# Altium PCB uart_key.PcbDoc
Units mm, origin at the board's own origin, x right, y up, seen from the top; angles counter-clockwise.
Board outline 80.99 x 54 mm, 2 copper layers (Top Layer, Bottom Layer); 61 components, 43 nets, 209 pads, 89 vias.
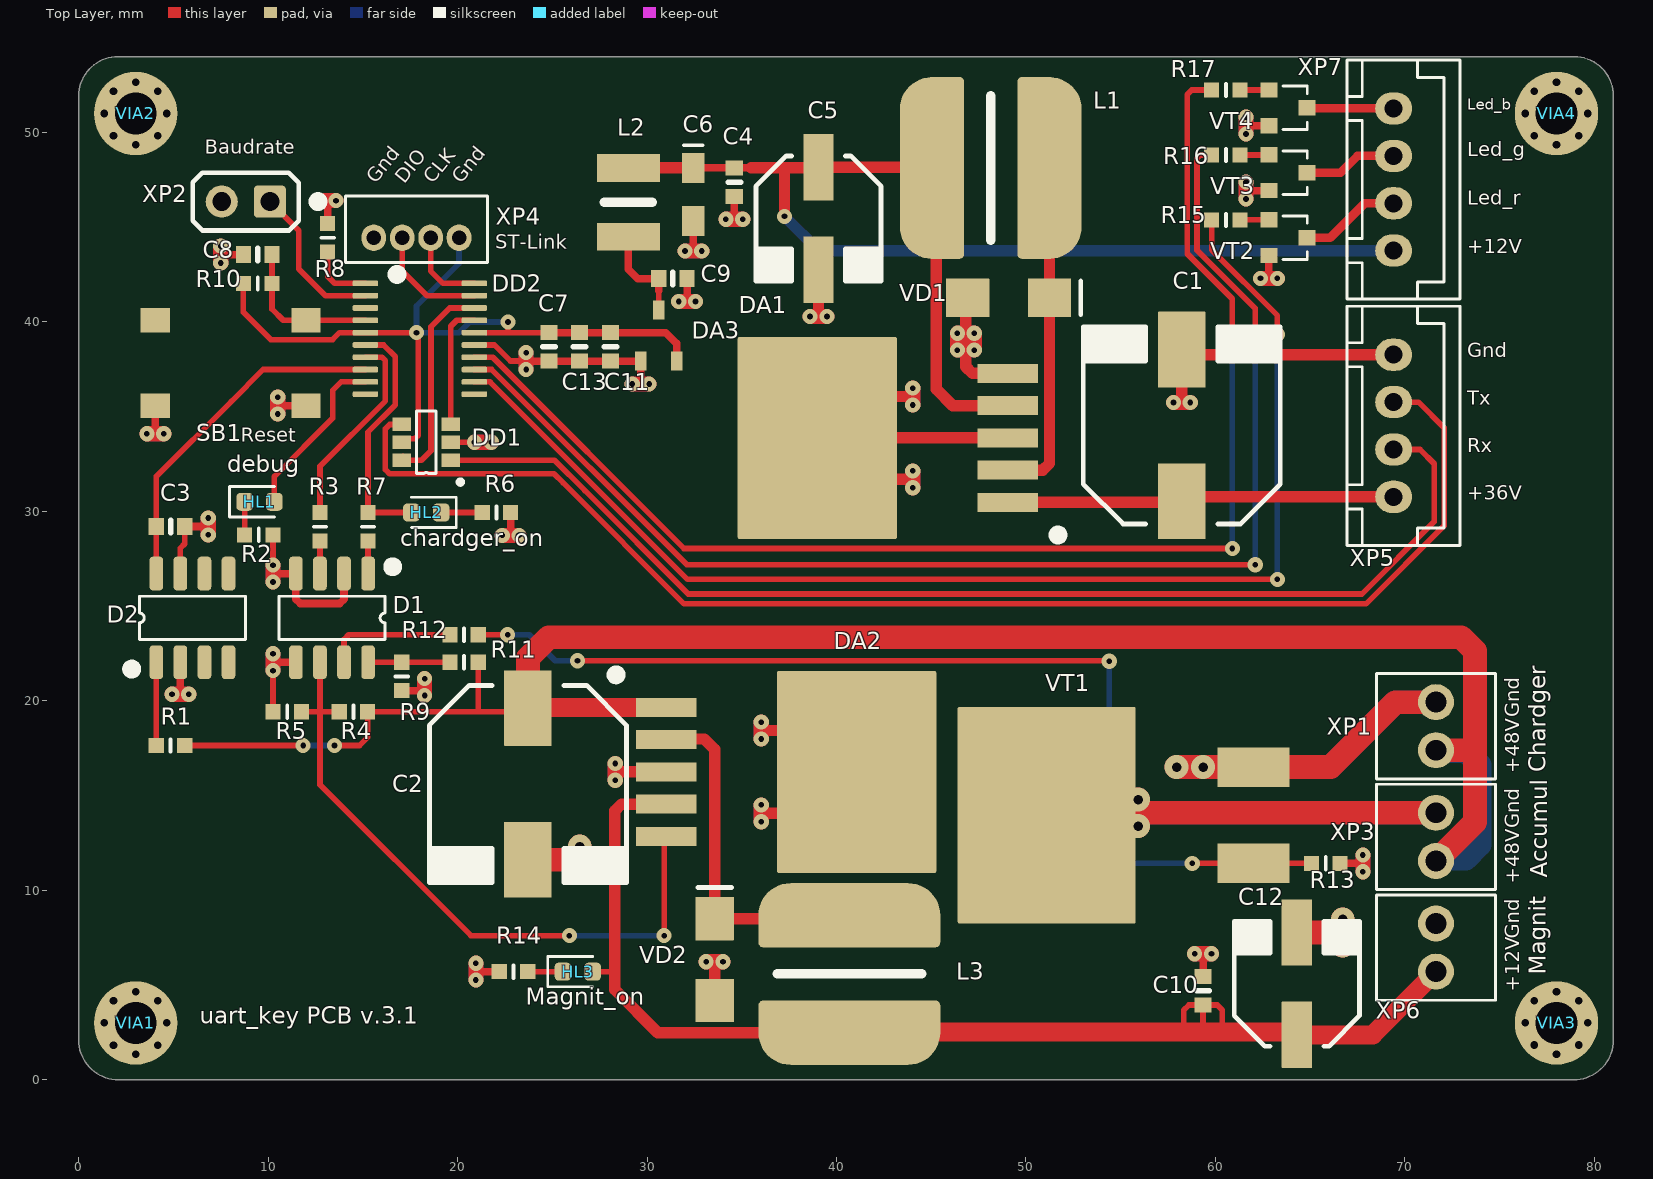
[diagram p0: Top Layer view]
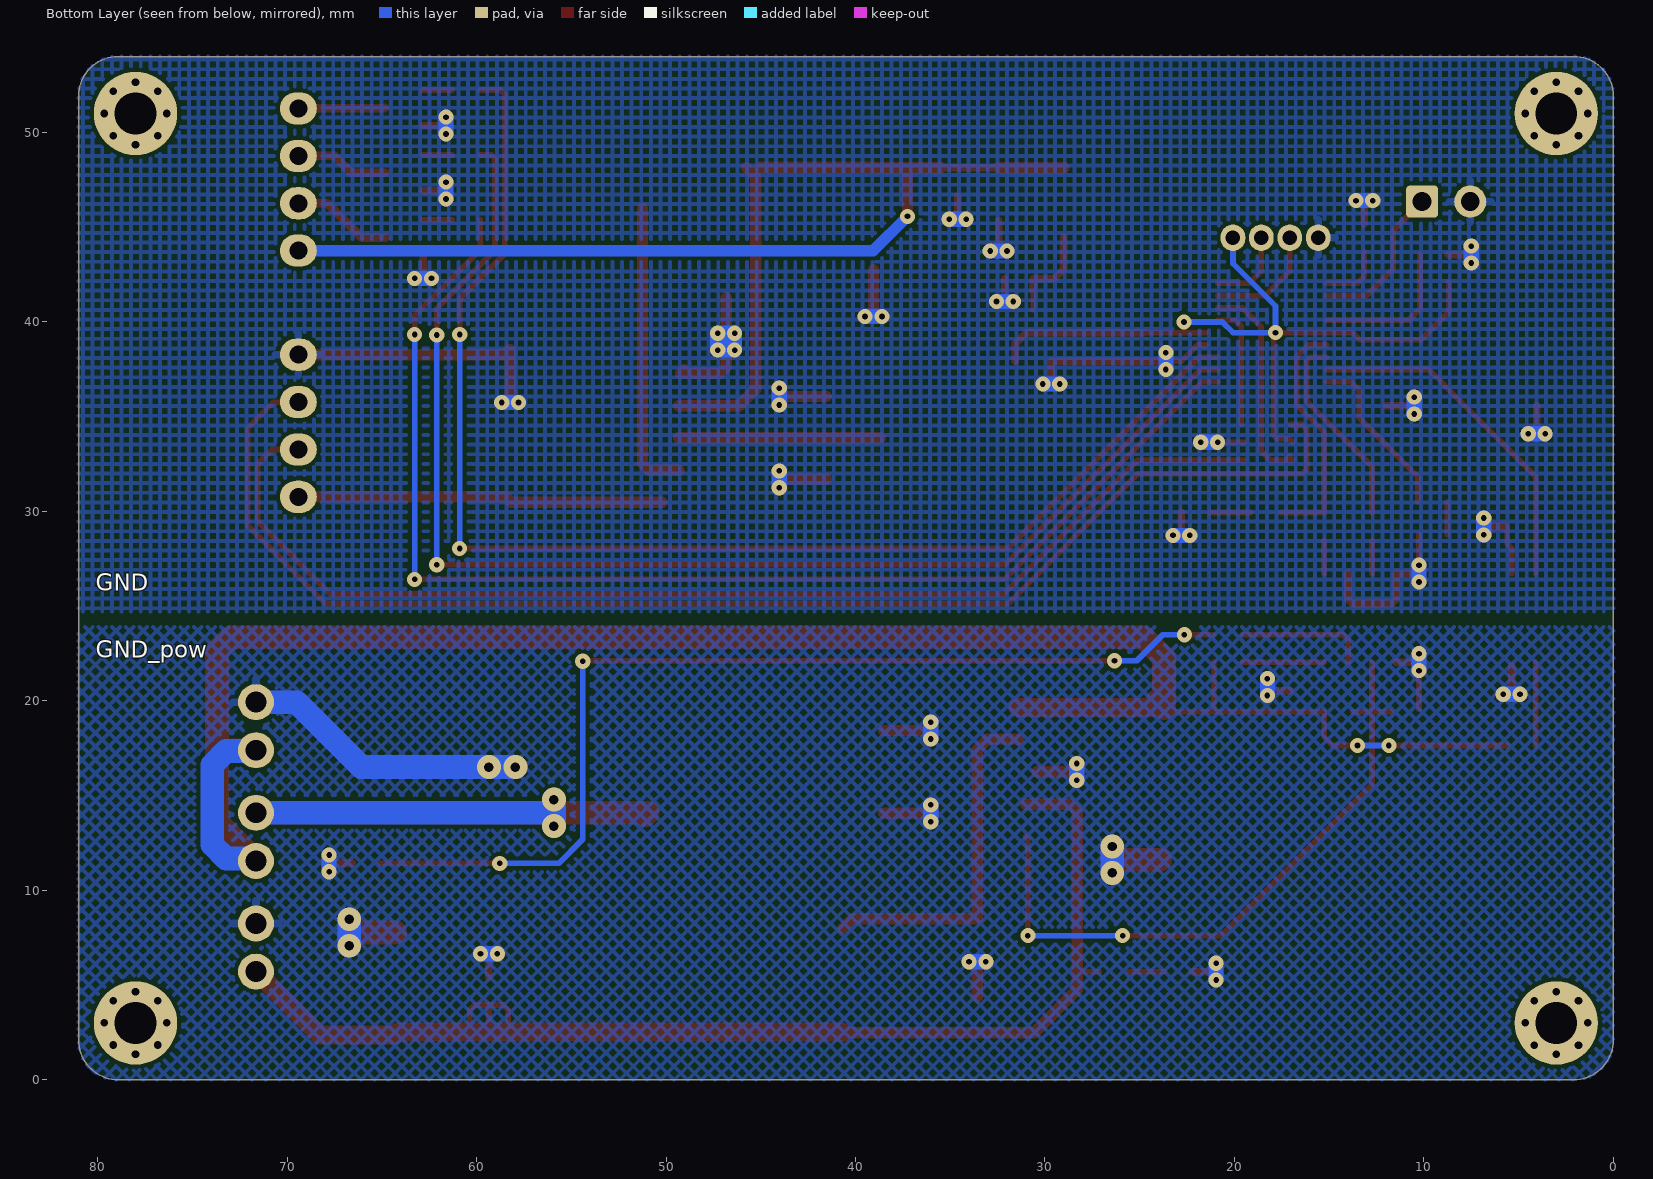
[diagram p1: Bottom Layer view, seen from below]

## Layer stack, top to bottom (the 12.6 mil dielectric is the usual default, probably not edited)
Top Solder: solder mask 0.0102, Solder Resist, Dk 3.5
Top Layer: signal copper 0.0356
Dielectric 1: dielectric 0.32, FR-4, Dk 4.8
Bottom Layer: signal copper 0.0356
Bottom Solder: solder mask 0.0102, Solder Resist, Dk 3.5

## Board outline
0.006,2.084 0.006,51.924 cw(c2.076,51.924) 2.076,53.994 78.931,53.994 cw(c78.93,51.924) 81,51.924 81,2.084 cw(c78.909,2.084) 78.909,-0.007 2.097,-0.006 cw(c2.097,2.084)

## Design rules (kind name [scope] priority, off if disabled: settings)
Clearance TestPointToPad [HasFootprint('TP_36_PAD') or HasFootprint('TP_38_PAD') or HasFootprint('TP_47_PAD') or HasFootprint('TP_50_PAD') or HasFootprint('TP_60_PAD') or HasFootprint('TP_80_PAD') or HasFootprint('TP_100_PAD') vs IsPad] p1: gap=0.22 ignorepadtopadclearanceinfootprint=FALSE except(0: Arc-Hole Track-Hole SMDPad-Hole THPad-Hole Via-Hole Fill-Hole Poly-Hole Region-Hole Text-Hole; 2: Arc-THPad Track-THPad SMDPad-THPad THPad-THPad)
Clearance [All] p2: gap=0.2 ignorepadtopadclearanceinfootprint=FALSE
ComponentClearance TestpointClearance [Footprint Like 'TP_36_PAD' or Footprint Like 'TP_38_PAD' or Footprint Like 'TP_47_PAD' or Footprint Like 'TP_50_PAD' or Footprint Like 'TP_60_PAD' or Footprint Like 'TP_80_PAD' or Footprint Like 'TP_100_PAD' vs Footprint Like 'TP_36_PAD' or Footprint Like 'TP_38_PAD' or Footprint Like 'TP_47_PAD' or Footprint Like 'TP_50_PAD' or Footprint Like 'TP_60_PAD' or Footprint Like 'TP_80_PAD' or Footprint Like 'TP_100_PAD'] p1: gap=0 collisioncheckmode=3 verticalgap=0.254 showdistances=FALSE
ComponentClearance [All] p2: gap=0.254 collisioncheckmode=3 verticalgap=0.254 showdistances=FALSE
DiffPairsRouting [All] p1: maxlimit=0.25 minlimit=0.2 mostfreqgap=0.22 toplayer_minwidth=0.2 toplayer_maxwidth=0.25 toplayer_prefwidth=0.22 bottomlayer_minwidth=0.2 bottomlayer_maxwidth=0.25 bottomlayer_prefwidth=0.22 maxuncoupledlength=12.7
HoleSize [All] p1: absolutevalues=TRUE maxlimit=4 minlimit=0.3 maxpercent=80.000 minpercent=20.000
MinimumSolderMaskSliver [All] p1: minsoldermaskwidth=0.1
PasteMaskExpansion [All] p1: expansion=-0.05
PlaneConnect [All] p1: planeconnectstyle=Relief reliefexpansion=0.508 reliefentries=4 reliefconductorwidth=0.4 reliefairgap=0.25
PolygonConnect PolygonConnect_1 [IsVia or InPadClass('Direct')] p1: connectstyle=Direct reliefconductorwidth=0.254 reliefentries=4 polygonreliefangle="90 Angle" airgapwidth=0.254
PolygonConnect [All] p2: connectstyle=Relief reliefconductorwidth=0.4 reliefentries=4 polygonreliefangle="90 Angle" airgapwidth=0.25
RoutingVias [All] p1: holewidth=0.3 width=1 viastyle="Through Hole" minholewidth=0.3 minwidth=0.7 maxholewidth=0.4 maxwidth=2.8
SilkToSilkClearance [All] p1: silktosilkclearance=0.2
SilkToSolderMaskClearance [IsPad] p1: minsilkscreentomaskgap=0.2 clearancetoexposedcopper=TRUE
SolderMaskExpansion [All] p1: expansion=0.1 istentingtop=FALSE
Width [All] p1: maxlimit=4 minlimit=0.22 preferedwidth=0.4
22 further rules are at their usual default settings.

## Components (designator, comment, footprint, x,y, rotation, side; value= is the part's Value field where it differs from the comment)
C1 "220uF 50V" CAPAE_SMD_1010 58.225,34.531 r270 top value=220uF
C2 "220uF 50V" CAPAE_SMD_1010 23.712,15.608 r90 top value=220uF
C3 "1uF 25V" CC0603_0.8mm 4.85,29.197 r0 top value=1uF
C4 "1uF 25V" CC0603_0.8mm 34.603,47.37 r270 top value=1uF
C5 "220uF 16V" CAPAE_SMD_0607 39.048,45.453 r90 top value=220uF
C6 "2.2uF 16V" TANT_3.2X1.6_A 32.444,46.72 r270 top value=2.2uF
C7 "0.15uF 50V" CC0603_0.8mm 24.824,38.677 r270 top value=0.15uF
C8 "1uF 25V" CC0603_0.8mm 9.457,43.548 r180 top value=1uF
C9 "10uF 25V" CC0603_0.8mm 31.365,42.278 r0 top value=10uF
C10 "1uF 25V" CC0603_0.8mm 59.345,4.686 r90 top value=1uF
C11 "10uF 25V" CC0603_0.8mm 28.075,38.677 r270 top value=10uF
C12 "220uF 16V" CAPAE_SMD_0607 64.298,5.067 r270 top value=220uF
C13 "0.15uF 50V" CC0603_0.8mm 26.424,38.677 r270 top value=0.15uF
D1 "MOCD217R2M" SO-8_height 13.371,24.371 r180 top
D2 "MOCD217R2M" SO-8_height 6.005,24.371 r0 top
DA1 "LM2596HVGR-12" "TO-263-5 (D2PAK)_2" 44.01,33.871 r180 top
DA2 "LM2596HVGR-12" "TO-263-5 (D2PAK)_2" 36.039,16.243 r0 top
DA3 "MCP1703T-3302E/CB" SOT-23A_MCP 30.615,39.277 r270 top value=3.3V
DD1 "SN74LVC2G14DBVR" SOT-23-6 18.347,33.642 r0 top
DD2 "STM32F042F6" TSSOP-20_ST 18.012,39.102 r270 top
HL1 "led_1608_green" led_1608 8.759,30.5 r0 top
HL2 "led_1608_red" led_1608 19.132,29.935 r180 top
HL3 "led_1608_red" led_1608 25.56,5.702 r0 top
L1 "SDR1006 33uH" SDR1006 48.14,48.12 r180 top value=33uH
L2 "LQH43C 15uH" LQH43C 29.015,46.3 r270 top value=15uH
L3 "SDR1006 33uH" SDR1006 40.676,5.58 r270 top value=33uH
R1 "10k ±1%" R0603 4.85,17.64 r0 top value=10k
R2 "10k ±1%" R0603 9.509,28.753 r0 top value=10k
R3 "100 ±1%" R0603 12.736,29.185 r270 top value=100
R4 "10k ±1%" R0603 14.502,19.418 r180 top value=10k
R5 "10k ±1%" R0603 11.009,19.418 r180 top value=10k
R6 "10k ±1%" R0603 22.05,29.935 r0 top value=10k
R7 "100 ±1%" R0603 15.276,29.185 r270 top value=100
R8 "10k ±1%" R0603 13.14,44.437 r270 top value=10k
R9 "10k ±1%" R0603 17.054,21.281 r270 top value=10k
R10 "10k ±1%" R0603 9.457,42.024 r0 top value=10k
R11 "10k ±1%" R0603 20.344,22.031 r0 top value=10k
R12 "100 ±1%" R0603 20.344,23.482 r0 top value=100
R13 "10k ±1%" R0603 65.822,11.417 r0 top value=10k
R14 "10k ±1%" R0603 22.951,5.702 r180 top value=10k
R15 "100 ±1%" R0603 60.548,45.377 r0 top value=100
R16 "100 ±1%" R0603 60.548,48.806 r0 top value=100
R17 "100 ±1%" R0603 60.548,52.235 r0 top value=100
SB1 "KLS7-TS6604-4.3-180" Tact_SMD_6x6h4.3 8.022,37.827 r0 top
VD1 "SS16" "DO-214AC (SMA)" 49.081,41.262 r180 top
VD2 "SS16" "DO-214AC (SMA)" 33.564,6.337 r270 top
VIA1 "via_circle_2.2mm" via_circle_2.2 3.006,2.994 r0 top
VIA2 "via_circle_2.2mm" via_circle_2.2 3.006,50.994 r0 top
VIA3 "via_circle_2.2mm" via_circle_2.2 78,2.994 r0 top
VIA4 "via_circle_2.2mm" via_circle_2.2 78,50.994 r0 top
VT1 "IRF630NSPBF" "TO-263A (D2PAK)" 53.495,13.957 r180 top
VT2 "IRLML2060" SOT-23 63.826,44.437 r180 top
VT3 "IRLML2060" SOT-23 63.826,47.866 r180 top
VT4 "IRLML2060" SOT-23 63.826,51.295 r180 top
XP1 "Зарядное устройство" DG308x2 71.638,17.386 r90 top
XP2 "Baudrate" PLS-2 8.822,46.342 r180 top
XP3 "На аккумулятор" DG308x2 71.638,11.544 r90 top
XP4 "ST-Link" B4B-ZR 20.077,44.437 r180 top
XP5 "COM" JST_XH_B4B-XH-A_1x04_P2.50mm_Vertical 69.401,30.761 r90 top
XP6 "Магнит" DG308x2 71.638,5.702 r90 top
XP7 "LED" JST_XH_B4B-XH-A_1x04_P2.50mm_Vertical 69.401,43.755 r90 top

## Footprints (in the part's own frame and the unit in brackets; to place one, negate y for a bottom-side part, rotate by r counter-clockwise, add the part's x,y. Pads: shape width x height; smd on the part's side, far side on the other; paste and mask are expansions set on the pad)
B4B-ZR [mm]
  oval 1.3x1.4 hole 0.762: 1(0,0) 2(1.5,0) 3(3,0) 4(4.5,0)
  silkscreen extent -1.5,-2.2 6,1.3, body extent -1.5,-2.2 6,1.3, height 4.5
CAPAE_SMD_0607 [mm] "SMD Aluminum Electrolytic Capacitor. DxL = 6.3x7.7mm."
  rrect2% 3.5x1.6 smd paste-10.05: 1(-2.7,0) 2(2.7,0)
  silkscreen extent -3.3,-3.3 3.3,3.3, body extent -3.6,-3.3 3.6,3.3, height 7.7
CAPAE_SMD_1010 [mm] "SMD Aluminum Electrolytic Capacitor. DxL = 10.0x10.0mm."
  rrect2% 4x2.5 smd paste-10.05: 1(-4,0) 2(4,0)
  silkscreen extent -5.2,-5.2 5.2,5.2, body extent -5.5,-5.2 5.5,5.2, height 10
CC0603_0.8mm [mm] "Yageo/ Radiused inverted home plate (RIHP) paste"
  rrect2% 0.8x0.9 smd paste-2: 1(-0.75,0) 2(0.75,0)
  Top Layer pour cut-out: -0.375,0.65 -0.375,-0.65 0.375,-0.65 0.375,0.65
  silkscreen extent 0,-0.33 0,0.33, body extent -0.8,-0.4 0.8,0.4, height 0.78
DG308x2 [mm]
  round 1.9 hole 1.1: 1(0,0) 2(2.54,0)
  silkscreen extent -1.51,-3.14 4.05,3.14, body extent -1.3,-3.2 3.78,3.1, height 8.54
"DO-214AC (SMA)" [mil]
  rrect2% 90x80 smd: 1(-85,0) 2(85,0)
  silkscreen extent -150,-35 -150,35, body extent -102,-51 102,51, height 95
JST_XH_B4B-XH-A_1x04_P2.50mm_Vertical [mm]
  oval 1.7x1.95 hole 0.95: 1(0,0) 2(2.5,0) 3(5,0) 4(7.5,0)
  silkscreen extent -2.56,-3.51 10.06,2.46, body extent -2.45,-3.4 9.95,2.35, height 7
led_1608 [mm]
  rrect50% 0.875x0.95 smd: 1(0,0) 2(1.57,0)
  silkscreen extent -0.8,-0.8 1.57,0.8, body extent 0,-0.4 1.6,0.4, height 1.1
LQH43C [mm] "Chip Inductor, 2-Leads, Body 4,50x3,20mm, IPC High Density"
  rect 1.46x3.32 smd paste-25: 1(-1.82,0) 2(1.82,0)
  silkscreen extent 0,-1.27 0,1.27, body extent -2.35,-1.6 2.35,1.6, height 2.6
PLS-2 [mm]
  rrect25% 1.7x1.7 hole 1: 1(-1.27,0)
  round 1.7 hole 1: 2(1.27,0)
  silkscreen extent -4.06,-1.52 2.79,1.52, body extent -2.54,-1.27 2.54,1.27, height 8.44
R0603 [mm]
  rect 0.8x0.8 smd paste-2: 1(-0.75,0) 2(0.75,0)
  Top Layer pour cut-out: -0.5,0.6 -0.5,-0.6 0.5,-0.6 0.5,0.6
  Top Layer pour cut-out: -0.5,0.6 0.5,0.6 0.5,-0.6 -0.5,-0.6
  silkscreen extent 0,-0.33 0,0.33, body extent -0.8,-0.4 0.8,0.4, height 0.37
SDR1006 [mm]
  oval 3.4x9.6 smd paste-5: 1(-3.1,0) 2(3.1,0)
  rrect25% 2x9.6 smd paste-5: 1(-2.4,0) 2(2.4,0)
  silkscreen extent 0,-3.81 0,3.81, body extent -4.89,-4.9 4.89,4.9, height 5.93
SO-8_height [mm] "SOIC, 8-Leads, Body 4.90x3.90mm, Pitch 1.27mm, IPC Medium Density"
  rrect50% 0.72x1.78 smd paste-0.05: 1(-1.905,-2.34) 2(-0.635,-2.34) 3(0.635,-2.34) 4(1.905,-2.34) 5(1.905,2.34) 6(0.635,2.34) 7(-0.635,2.34) 8(-1.905,2.34)
  silkscreen extent -3.45,-2.95 2.79,1.14, body extent -2.92,-2.96 2.92,2.96, height 3.33
SOT-23 [mil]
  rrect2% 36x32 smd: 1(39.5,-37) 2(39.5,37) 3(-39.5,0)
  silkscreen extent -40,-45 10,45, body extent -49,-59 49,59, height 43
SOT-23-6 [mm] "SOT23, 6-Leads, Body 2.92x2.84mm, Pitch 0.95mm, IPC Medium Density"
  rrect2% 0.99x0.69 smd paste-0.05 mask+0.05: 1(1.295,-0.95) 2(1.295,0) 3(1.295,0.95) 4(-1.295,0.95) 5(-1.295,0) 6(-1.295,-0.95)
  silkscreen extent -0.51,-2.22 1.92,1.65, body extent -1.5,-1.5 1.5,1.5, height 1.3
SOT-23A_MCP [mm] "Посадочное место под SOT-23A. Рекомендации MicroChip"
  rrect2% 1x0.6 smd: 1(1.35,-0.95) 2(1.35,0.95) 3(-1.35,0)
  body extent -1.5,-1.52 1.5,1.52, height 1.32
Tact_SMD_6x6h4.3 [mm] "6x6mm Tact Switch, H=4.3mm"
  rrect2% 1.55x1.3 smd: COM(-3.975,2.25) COM(3.975,2.25) NO(-3.975,-2.25) NO(3.975,-2.25)
  body extent -4.5,-3.1 4.5,3.1, height 4.3
TANT_3.2X1.6_A [mm] "SMD Aluminum Electrolytic Capacitor. DxL = 6.3x7.7mm."
  rrect2% 1.6x1.2 smd: 1(1.4,0) 2(-1.4,0)
  silkscreen extent -2.6,-0.5 -2.6,0.5, body extent -1.6,-0.8 1.6,0.8, height 1.6
"TO-263-5 (D2PAK)_2" [mm] "D2-PAK, 6-Pads, Body 7,77x8,48mm (max), IPC Medium Density"
  rrect2% 3.2x1 smd: 1(-5.025,3.4) 2(-5.025,1.7) 3(-5.025,0) 4(-5.025,-1.7) 5(-5.025,-3.4)
  rrect2% 8.4x10.66 smd paste-25: 6(5.025,0)
  silkscreen extent -7.92,4.88 -7.43,5.37, body extent -5.12,-5.08 8.89,5.08, height 4.56
"TO-263A (D2PAK)" [mm]
  rrect2% 3.81x2.08 smd: 1(-8.517,2.54) 3(-8.517,-2.54)
  rrect2% 9.398x11.43 smd paste-20: 2(2.405,0)
  body extent -9.86,-5.32 5.99,5.32, height 4.8
TSSOP-20_ST [mm] "TSSOP, 20-Leads, Body 6.50x4.40mm, Pitch 0.65mm, ST recommend footprint"
  rrect50% 0.3x1.35 smd paste-0.025 mask+0.075: 1(-2.925,-2.875) 2(-2.275,-2.875) 3(-1.625,-2.875) 4(-0.975,-2.875) 5(-0.325,-2.875) 6(0.325,-2.875) 7(0.975,-2.875) 8(1.625,-2.875) 9(2.275,-2.875) 10(2.925,-2.875) 11(2.925,2.875) 12(2.275,2.875) 13(1.625,2.875) 14(0.975,2.875) 15(0.325,2.875) 16(-0.325,2.875) 17(-0.975,2.875) 18(-1.625,2.875) 19(-2.275,2.875) 20(-2.925,2.875)
  silkscreen extent -3.65,-1.46 -3.15,-0.96, body extent -3.25,-3.21 3.25,3.21, height 0.98
via_circle_2.2 [mm]
  round 0.7 hole 0.4: 1(-1.649,0) 1(-1.166,-1.166) 1(-1.166,1.167) 1(0,-1.65) 1(0,1.65) 1(1.167,-1.166) 1(1.167,1.167) 1(1.651,0)
  round 4.4 hole 2.2: 1(0,0)

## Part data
C1 C2: library part Capacitor_elec, Tolerance=±10%, Voltage=50V
C3 C4 C8 C9 C10 C11: library part Capacitor, Tolerance=±10%, Voltage=25V
C5 C6 C12: library part Capacitor_elec, Tolerance=±10%, Voltage=16V
C7 C13: library part Capacitor, Tolerance=±10%, Voltage=50V
DD2: "ARM-based 32-bit MCU, up to 32 KB Flash, crystal-less USB  FS 2.0, CAN, 8 timers, ADC & comm. interfaces, 2.0 - 3.6 V"
L1 L2 L3: library part Inductor
R1 R2 R3 R4 R5 R6 R7 R8 R9 R10 R11 R12 R13 R14 R15 R16 R17: library part Res_0603, Tolerance=±1%
SB1: library part Tact_6х6х4.3_SMD
XP1 XP3 XP6: library part DG308x2
XP2: library part Conn_01_02pin
XP4: library part B4B-ZR_conn_01x04_st_link
XP5 XP7: library part JST_XH_B4B-XH-A_1x04_P2.50mm_Vertical

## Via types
v1: diameter 0.8, hole 0.3, Top Layer to Bottom Layer, tented both sides, 81 vias
v2: diameter 1.25, hole 0.5, Top Layer to Bottom Layer, tented both sides, 4 vias
v3: diameter 1.25, hole 0.5, Top Layer to Bottom Layer, 2 vias
v4: diameter 1.25, hole 0.5, Top Layer to Bottom Layer, tented top, 2 vias

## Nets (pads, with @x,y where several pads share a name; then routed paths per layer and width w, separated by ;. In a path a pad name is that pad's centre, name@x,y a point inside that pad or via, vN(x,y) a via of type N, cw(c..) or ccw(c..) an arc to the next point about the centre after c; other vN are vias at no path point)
+3.3V: C7.1 C11.1 C13.1 DA3.2 DD1.5 DD2.5 DD2.16 R10.1 XP4.1 | length 40.9
  Top Layer w0.3: R10.1@8.695,42.109 8.695,40.5 10.138,39.057 13.405,39.057 13.775,39.427 DD2.5 v1(17.831,39.427) 17.917,39.341 17.917,34.001 17.741,33.825 17.108,33.825 DD1.5@16.925,33.642 ; DD2.16@21.522,39.427 22.665,39.427 ; v1(22.665,39.992) 22.665,39.427 ; C7.1 22.665,39.427
  Top Layer w0.4: C7.1 C13.1 C11.1 30.99,39.427 31.565,38.852 DA3.2
  Bottom Layer w0.3: XP4.1 20.077,43.077 17.831,40.831 v1(17.831,39.427) 20.077,39.427 20.642,39.992 v1(22.665,39.992)
+12V: C4.1 C5.2 C6.2 DA1.4 L1.2 L2.1 XP7.1 | length 67.8
  Top Layer w0.4: C6.2 C4.1 35.492,48.12
  Top Layer w0.6: L2.1 C6.2 ; 35.492,48.12 37.254,48.12 ; v1(37.254,45.564) 37.254,48.12 ; L1.2@45.04,48.12 45.007,48.153 C5.2 39.015,48.12 37.254,48.12 ; L1.2@45.74,48.12 45.259,47.639 45.259,36.448 46.135,35.573 DA1.4@49.335,35.573
  Bottom Layer w0.6: v1(37.254,45.564) 39.062,43.755 XP7.1
+12V_magnit: C10.1 C12.2 DA2.4 HL3.2 L3.2 XP6.1 | length 65.6
  Top Layer w0.3: HL3.2 28.273,5.702 ; 58.329,2.367 58.329,2.523 58.329,3.67 58.595,3.936 C10.1 ; 59.345,2.367 59.345,2.523 C10.1 ; 60.361,2.367 60.361,2.523 60.361,3.67 60.095,3.936 C10.1
  Top Layer w0.6: DA2.4 31.012,14.542 28.651,14.542 28.3,14.19 28.3,4.743 30.563,2.48 L3.2@40.676,2.48
  Top Layer w1: L3.2@40.676,2.48 40.718,2.523 58.329,2.523 59.345,2.523 60.361,2.523 64.143,2.523 C12.2 68.303,2.367 XP6.1
+36V: C1.2 DA1.1 XP5.1 | length 19.3
  Top Layer w0.6: DA1.1@50.224,30.467 58.161,30.467 C1.2 58.455,30.761 XP5.1
+48V_charger: C2.2 DA2.1 R1.2 R4.1 R11.2 XP1.1 XP3.1 | length 107.3
  Top Layer w0.3: R1.2 v1(11.847,17.64) ; v1(13.506,17.64) 14.826,17.64 15.252,18.066 R4.1 ; R4.1@15.276,19.418 21.118,19.418 ; R11.2 21.094,19.442 21.118,19.418 ; C2.2@23.849,19.418 21.118,19.418
  Top Layer w1: C2.2@23.951,19.647 DA2.1@31.414,19.647
  Top Layer w1.25: C2.2@24.084,19.981 C2.2 23.712,22.251 24.816,23.355 72.964,23.355 73.696,22.623 73.696,17.386 ; XP3.1 73.696,13.602 73.696,17.386 ; XP1.1 73.696,17.386
  Bottom Layer w0.3: v1(11.847,17.64) v1(13.506,17.64)
  Bottom Layer w1.25: XP3.1 71.762,11.669 73.218,11.669 73.95,12.401 73.95,16.612 73.218,17.344 71.68,17.344 XP1.1
baud: DD2.2 XP2.1 | length 8.3
  Top Layer w0.3: XP2.1 11.616,44.818 11.616,42.786 13.025,41.377 DD2.2
CLK: DD2.20 XP4.2 | length 4.3
  Top Layer w0.3: XP4.2 18.577,42.683 19.233,42.027 DD2.20
DIO: DD2.19 XP4.3 | length 6.1
  Top Layer w0.3: XP4.3 17.077,42.683 18.383,41.377 DD2.19
GND: C1.1 C3.2 C4.2 C5.1 C6.1 C7.2 C8.2 C9.2 C11.2 C13.2 D1.2 D1.4 D2.7 DA1.3 DA1.5 DA1.6 DA3.1 DD1.2 DD2.15 R2.2 R6.2 R8.1 SB1.NO VD1.2 VT2.2 VT3.2 VT4.2 XP2.2 XP4.4 XP5.4 | length 119.1
  Top Layer w0.3: D2.7 5.37,28.054 5.6,28.284 C3.2 ; v1(10.259,27.156) R2.2 ; DD1.2@19.515,33.642 DD1.2 v1(20.887,33.642) ; DD2.15@21.522,38.777 21.941,38.777 22.791,37.927 23.618,37.927
  Top Layer w0.4: 4.047,34.087 SB1.NO@4.047,35.577 ; C3.2@5.727,29.197 6.842,29.197 ; 7.501,43.548 C8.2 ; 10.259,26.711 D1.4 11.466,25.368 11.7,25.133 13.772,25.133 14.006,25.368 D1.2 ; 10.507,35.577 SB1.NO@11.997,35.577 ; R8.1 13.14,46.394 ; 22.8,28.729 R6.2 ; 23.618,37.927 C7.2 C13.2 C11.2 DA3.1 29.665,36.721 ; 32.115,41.072 C9.2 ; 32.444,43.739 C6.1 ; 34.603,45.414 C4.2 ; 61.616,46.927 VT3.2 ; 61.616,50.356 VT4.2 ; 62.822,42.291 VT2.2
  Top Layer w0.6: DA1.6@38.685,33.871 DA1.3@49.335,33.871 ; 39.048,40.277 C5.1 ; DA1.6@41.545,31.686 44.022,31.686 ; DA1.6@41.545,36.055 44.022,36.055 ; 46.822,38.405 46.822,37.626 47.173,37.275 49.031,37.275 DA1.5 ; 46.822,38.949 VD1.2@46.822,41.262 ; DA1.5@49.039,37.471 DA1.5@49.235,37.275 ; 58.225,35.738 C1.1@58.225,38.396 ; C1.1 58.495,38.261 XP5.4
  Top Layer w0.8: v1(3.603,34.087) 4.047,34.087 v1(4.492,34.087) ; v1(6.842,28.753) 6.842,29.197 v1(6.842,29.642) ; v1(7.501,43.104) 7.501,43.548 v1(7.501,43.993) ; v1(10.259,26.267) 10.259,26.711 v1(10.259,27.156) ; v1(10.507,35.133) 10.507,35.577 v1(10.507,36.022) ; v1(12.696,46.394) 13.14,46.394 v1(13.585,46.394) ; v1(20.887,33.642) v1(21.776,33.642) ; v1(22.356,28.729) 22.8,28.729 v1(23.245,28.729) ; v1(23.618,37.483) 23.618,37.927 v1(23.618,38.372) ; v1(29.221,36.721) 29.665,36.721 v1(30.11,36.721) ; v1(31.671,41.072) 32.115,41.072 v1(32.56,41.072) ; v1(32,43.739) 32.444,43.739 v1(32.889,43.739) ; v1(34.159,45.414) 34.603,45.414 v1(35.048,45.414) ; v1(38.604,40.277) 39.048,40.277 v1(39.493,40.277) ; v1(44.022,31.242) 44.022,31.686 v1(44.022,32.131) ; v1(44.022,35.611) 44.022,36.055 v1(44.022,36.5) ; 46.822,38.505 v1(46.378,38.505) v1(46.378,39.394) v1(47.267,39.394) v1(47.267,38.505) 46.822,38.949 ; v1(57.781,35.738) 58.225,35.738 v1(58.67,35.738) ; v1(61.616,46.482) 61.616,46.927 v1(61.616,47.371) ; v1(61.616,49.911) 61.616,50.356 v1(61.616,50.8) ; v1(62.378,42.291) 62.822,42.291 v1(63.267,42.291)
  Bottom Layer w0.8: v1(3.603,34.087) v1(4.492,34.087) ; v1(6.842,28.753) v1(6.842,29.642) ; v1(7.501,43.104) v1(7.501,43.993) ; v1(10.259,26.267) v1(10.259,27.156) ; v1(10.507,35.133) v1(10.507,36.022) ; v1(12.696,46.394) v1(13.585,46.394) ; v1(20.887,33.642) v1(21.776,33.642) ; v1(22.356,28.729) v1(23.245,28.729) ; v1(23.618,37.483) v1(23.618,38.372) ; v1(29.221,36.721) v1(30.11,36.721) ; v1(31.671,41.072) v1(32.56,41.072) ; v1(32,43.739) v1(32.889,43.739) ; v1(34.159,45.414) v1(35.048,45.414) ; v1(38.604,40.277) v1(39.493,40.277) ; v1(44.022,31.242) v1(44.022,32.131) ; v1(44.022,35.611) v1(44.022,36.5) ; v1(57.781,35.738) v1(58.67,35.738) ; v1(61.616,46.482) v1(61.616,47.371) ; v1(61.616,49.911) v1(61.616,50.8) ; v1(62.378,42.291) v1(63.267,42.291) ; v1(46.378,38.505) v1(47.267,39.394) ; v1(46.378,38.505) v1(47.267,38.505) v1(47.267,39.394) ; v1(46.378,38.505) v1(46.378,39.394) v1(47.267,39.394)
GND_pow: C2.1 C10.2 C12.1 D1.5 D2.2 DA2.3 DA2.6 R5.2 R9.2 R13.2 R14.2 VD2.2 VT1.3 XP1.2 XP6.2 | length 77
  Top Layer w0.3: R5.2@10.259,19.545 v1(10.259,21.587)
  Top Layer w0.4: 5.37,20.341 D2.2@5.37,21.831 ; 10.259,22.031 D1.5 ; R9.2 v1@18.26,20.531 ; 20.964,5.702 R14.2 ; C10.2 59.345,6.643 ; R13.2 67.778,11.417
  Top Layer w0.6: 28.318,16.243 DA2.3@30.414,16.243 ; VD2.2@33.564,4.378 33.564,6.22 ; 36.027,14.059 DA2.6@38.504,14.059 ; 36.027,18.428 DA2.6@38.504,18.428
  Top Layer w0.8: v1(4.925,20.341) 5.37,20.341 v1(5.814,20.341) ; v1(10.259,21.587) 10.259,22.031 v1(10.259,22.476) ; v1(18.26,20.277) 18.26,20.531 v1(18.26,21.166) ; v1(20.964,5.258) 20.964,5.702 v1(20.964,6.147) ; v1(28.318,15.799) 28.318,16.243 v1(28.318,16.688) ; v1(33.119,6.22) 33.564,6.22 v1(34.008,6.22) ; v1(36.027,13.614) 36.027,14.059 v1(36.027,14.503) ; v1(36.027,17.983) 36.027,18.428 v1(36.027,18.872) ; v1(58.9,6.643) 59.345,6.643 v1(59.789,6.643) ; v1(67.778,10.973) 67.778,11.417 v1(67.778,11.862)
  Top Layer w1.25: C2.1@23.912,11.608 26.452,11.608 ; v2(26.452,10.91) 26.452,11.608 ; v2(26.452,12.307) 26.452,11.608 ; v4(57.948,16.497) v4(59.345,16.497) VT1.3 66.076,16.497 69.505,19.926 XP1.2 ; C12.1 66.711,7.767 ; v2(66.711,7.069) 66.711,7.767 ; v2(66.711,8.466) 66.711,7.767
  Bottom Layer w0.8: v1(4.925,20.341) v1(5.814,20.341) ; v1(10.259,21.587) v1(10.259,22.476) ; v1(18.26,20.277) v1(18.26,21.166) ; v1(20.964,5.258) v1(20.964,6.147) ; v1(28.318,15.799) v1(28.318,16.688) ; v1(33.119,6.22) v1(34.008,6.22) ; v1(36.027,13.614) v1(36.027,14.503) ; v1(36.027,17.983) v1(36.027,18.872) ; v1(58.9,6.643) v1(59.789,6.643) ; v1(67.778,10.973) v1(67.778,11.862)
  Bottom Layer w1.25: v2(26.452,10.91) v2(26.452,12.307) ; v4(57.948,16.497) v4(59.345,16.497) 66.076,16.497 69.505,19.926 XP1.2 ; v2(66.711,7.069) v2(66.711,8.466)
is_chardger: C3.1 D2.8 DD2.8 | length 18.5
  Top Layer w0.3: D2.8 C3.1 4.1,31.841 8.06,35.801 9.736,37.477 DD2.8
led_b_on: DD2.14 R17.1 | length 70.5
  Top Layer w0.3: DD2.14 21.856,38.127 31.944,28.039 v1(60.892,28.039) ; R17.1 58.746,52.235 58.508,51.998 58.508,43.592 60.888,41.212 v1(60.888,39.326)
  Bottom Layer w0.3: v1(60.888,39.326) 60.89,39.324 60.89,28.041 v1(60.892,28.039)
led_b_power: VT4.3 XP7.4 | length 4.6
  Top Layer w0.45: VT4.3 64.849,51.275 69.381,51.275 XP7.4
led_g_on: DD2.13 R16.1 | length 69.1
  Top Layer w0.3: DD2.13 21.799,37.477 32.103,27.173 v1(62.1,27.173) ; R16.1 59.204,48.806 59.028,48.63 59.028,43.779 62.1,40.707 v1(62.1,39.3)
  Bottom Layer w0.3: v1(62.1,27.173) v1(62.1,39.3)
led_g_power: VT3.3 XP7.3 | length 4.9
  Top Layer w0.4: XP7.3@69.395,48.749 XP7.3
  Top Layer w0.45: VT3.3 66.607,47.866 67.496,48.755 XP7.3
led_r_on: DD2.12 R15.1 | length 67.1
  Top Layer w0.3: DD2.12 21.713,36.827 32.137,26.403 v1(63.267,26.403) ; R15.1 59.798,43.802 63.267,40.333 v1(63.267,39.326)
  Bottom Layer w0.3: v1(63.267,26.403) v1(63.267,39.326)
led_r_power: VT2.3 XP7.2 | length 5.3
  Top Layer w0.45: VT2.3 66.059,44.437 67.877,46.255 XP7.2
NetC8_1: C8.1 DD2.4 R10.2 SB1.COM | length 8.1
  Top Layer w0.3: C8.1 R10.2 10.207,40.669 10.799,40.077 DD2.4
NetC9_1: C9.1 DA3.3 L2.2 | length 5.2
  Top Layer w0.3: DA3.3 30.615,41.628
  Top Layer w0.4: L2.2 29.015,42.785 29.522,42.278 C9.1 30.615,41.628
NetD1_1: D1.1 R7.2 | length 1.7
  Top Layer w0.3: D1.1 R7.2
NetD1_3: D1.3 R3.2 | length 1.7
  Top Layer w0.3: D1.3 R3.2
NetD1_6: D1.6 DA2.5 R4.2 R5.1 | length 35.2
  Top Layer w0.3: R5.1 12.736,19.418 ; D1.6 12.736,19.418 ; R4.2 12.736,19.418 ; v1(25.9,7.6) 20.7,7.6 12.736,15.564 12.736,19.418 ; v1(30.9,7.6) 30.9,12.729 DA2.5
  Bottom Layer w0.3: v1(25.9,7.6) v1(30.9,7.6)
NetD1_7: D1.7 R12.1 | length 6.9
  Top Layer w0.3: D1.7 14.006,23.228 14.26,23.482 R12.1
NetD1_8: D1.8 R9.1 R11.1 | length 4.3
  Top Layer w0.3: D1.8 R9.1 R11.1
NetD2_1: D2.1 R1.1 | length 4.4
  Top Layer w0.3: R1.1 D2.1
NetDA1_2: DA1.2 L1.1 VD1.1 | length 15.5
  Top Layer w0.6: DA1.2@49.335,32.169 50.889,32.169 51.24,32.521 VD1.1 51.24,45.274 L1.1@51.24,45.974
NetDA2_2: DA2.2 L3.1 VD2.1 | length 18.7
  Top Layer w0.6: DA2.2@31.414,17.945 31.452,17.983 33.018,17.983 33.564,17.437 VD2.1 40.16,8.496 L3.1@40.676,7.98
NetDD2_1: DD2.1 R8.2 | length 3.4
  Top Layer w0.3: R8.2 13.14,42.405 13.518,42.027 DD2.1
NetDD2_9: DD2.9 HL1.2 | length 9.1
  Top Layer w0.3: HL1.2 10.329,31.832 13.405,34.908 13.405,36.38 13.852,36.827 DD2.9
NetHL1_1: HL1.1 R2.1 | length 1.7
  Top Layer w0.3: R2.1 HL1.1
NetHL2_1: HL2.1 R6.1 | length 2.2
  Top Layer w0.3: HL2.1 R6.1
NetHL3_1: HL3.1 R14.1 | length 1.9
  Top Layer w0.3: R14.1 HL3.1
NetR12_2: R12.2 R13.1 VT1.1 | length 54.5
  Top Layer w0.3: R12.2 v1(22.642,23.482) ; v1(26.325,22.11) 54.367,22.11 v1(54.392,22.085) ; v1(58.773,11.417) VT1.1 R13.1
  Bottom Layer w0.3: v1(22.642,23.482) 23.785,23.482 25.157,22.11 v1(26.325,22.11) ; v1(54.392,22.085) 54.392,12.687 55.662,11.417 v1(58.773,11.417)
NetR15_2: R15.2 VT2.1 | length 1.5
  Top Layer w0.3: R15.2 VT2.1
NetR16_2: R16.2 VT3.1 | length 1.5
  Top Layer w0.3: R16.2 VT3.1
NetR17_2: R17.2 VT4.1 | length 1.5
  Top Layer w0.3: R17.2 VT4.1
NetVT1_2: VT1.2 XP3.2 | length 39.3
  Top Layer w1.25: VT1.2@50.963,14.084 VT1.2 51.217,14.084 55.916,14.084 ; v3(55.916,13.386) 55.916,14.084 ; v3(55.916,14.783) 55.916,14.084 ; XP3.2 55.916,14.084
  Bottom Layer w1.25: v3(55.916,13.386) 55.916,14.084 ; v3(55.916,14.783) 55.916,14.084 ; XP3.2 55.916,14.084
on_chardger: DD2.6 HL2.2 R7.1 | length 12.9
  Top Layer w0.3: DD2.6 16.097,38.777 16.707,38.167 16.707,35.607 15.276,34.176 R7.1 HL2.2
on_magnit: DD2.7 R3.1 | length 10.6
  Top Layer w0.3: R3.1 12.736,32.371 16.187,35.822 16.187,37.952 16.011,38.127 DD2.7
rx: DD1.6 DD2.18 | length 11.4
  Top Layer w0.3: DD1.6@17.12,32.887 16.925,32.692 18.1,32.692 18.601,33.193 18.601,33.388 18.601,39.738 19.59,40.727 DD2.18
rx_clem: DD1.1 XP5.2 | length 62.1
  Top Layer w0.3: DD1.1@19.515,32.692 25.113,32.692 26.716,31.089 32.172,25.633 67.729,25.633 71.548,29.453 71.548,32.511 70.798,33.261 XP5.2
tx: DD1.3 DD2.17 | length 6.5
  Top Layer w0.3: DD1.3 19.642,39.763 19.956,40.077 DD2.17
tx_clem: DD1.4 XP5.3 | length 72.3
  Top Layer w0.3: DD1.4@16.73,34.397 DD1.4@16.915,34.582 ; DD1.4@16.925,34.592 DD1.4@16.915,34.582 ; DD1.4 17.042,34.582 DD1.4@16.915,34.582 ; XP5.3 70.711,35.761 72.068,34.404 72.068,29.237 67.944,25.113 31.957,25.113 25.586,31.484 25.093,31.977 16.408,31.977 16.187,32.198 16.187,34.351 16.418,34.582 DD1.4@16.915,34.582
pads on no net: D2.3 D2.4 D2.5 D2.6 DD2.3 DD2.10 DD2.11 VIA1.1 VIA2.1 VIA3.1 VIA4.1

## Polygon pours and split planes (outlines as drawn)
GND_pow on Bottom Layer "GND_POW_L02_P006" (hatched 45Degree grid 0.508 track 0.203, remove dead copper, pour order 6): 0.006,2.084 ccw(c2.097,2.084) 2.097,-0.006 78.9,-0.006 ccw(c78.905,2.089) 81,2.084 81,23.9 0,23.9
GND on Bottom Layer "GND_L02_P005" (hatched 90Degree grid 0.508 track 0.203, remove dead copper, pour order 5): 0,24.7 81,24.7 81,51.924 ccw(c78.931,51.924) 78.931,53.993 2.076,53.994 ccw(c2.076,51.924) 0.006,51.924

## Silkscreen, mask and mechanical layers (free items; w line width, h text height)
Top Overlay:
  text "Led_b" at 73.3,50.991 h1
  text "Baudrate" at 6.652,48.6 h1.3 r359.86
  text "Led_g" at 73.3,48.471 h1.3
  text "Gnd" at 15.892,47.079 h1.3 r51.06
  text "DIO" at 17.392,47.079 h1.3 r51.06
  text "CLK" at 18.892,47.079 h1.3 r51.06
  text "Gnd" at 20.392,47.079 h1.3 r51.06
  text "Led_r" at 73.3,45.912 h1.3
  text "ST-Link" at 21.999,43.596 h1.3 r359.86
  text "+12V" at 73.3,43.347 h1.3
  text "Gnd" at 73.3,37.856 h1.3
  text "Tx" at 73.3,35.356 h1.3
  text "Reset" at 8.563,33.403 h1.3 r359.86
  text "Rx" at 73.3,32.856 h1.3
  text "debug" at 7.832,31.767 h1.52
  text "+36V" at 73.3,30.356 h1.3
  text "chardger_on" at 16.968,27.867 h1.52
  text "Gnd" at 76.3,19.116 h1.3 r90
  text "Chardger" at 77.715,16.212 h1.52 r90
  text "+48V" at 76.3,16.172 h1.3 r90
  text "Gnd" at 76.3,13.274 h1.3 r90
  text "Accumul" at 77.8,10.658 h1.52 r90
  text "+48V" at 76.3,10.33 h1.3 r90
  text "Gnd" at 76.3,7.432 h1.3 r90
  text "Magnit" at 77.715,5.541 h1.52 r90
  text "+12V" at 76.3,4.65 h1.3 r90
  text "Magnit_on" at 23.591,3.665 h1.52
  text "uart_key PCB v.3.1" at 6.4,2.663 h1.52
Bottom Overlay:
  text "GND" at 80.1,25.524 h1.52
  text "GND_pow" at 80.1,21.967 h1.52
Mechanical 1:
  the board outline again, w0.013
